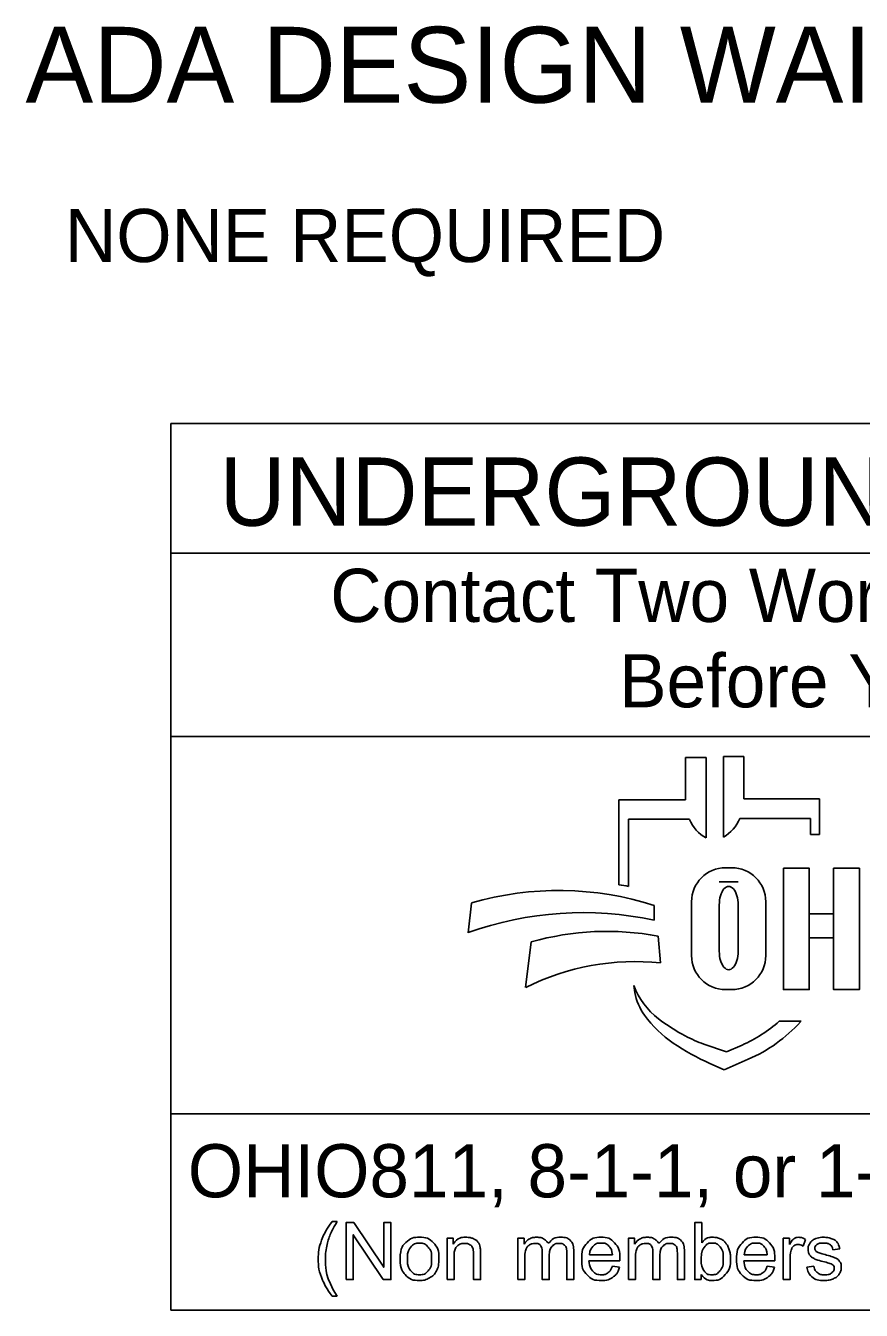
# Model space of a CAD drawing. Extents: x 0 to 40.2, y 0 to 22.
# Drawn here: x 1.995 to 4.196, y 2.143 to 5.529 of the extents above; entities that cross this region are included whole.
import ezdxf

# ---------------------------------------------------------------- set-up
doc = ezdxf.new("R2010")
doc.units = 0
doc.layers.add('GM_X_Adjacent_County', color=7, linetype='Continuous')
doc.layers.add('GM_X_Adjacent_County_Text', color=7, linetype='Continuous')

msp = doc.modelspace()

# ---------------------------------------------------------------- linework, layer by layer
at = {"layer": 'GM_X_Adjacent_County'}
for p, q in [((2.3775, 2.1428), (2.3775, 4.4803)), ((6.6275, 4.4803), (2.3775, 4.4803)), ((2.3775, 4.1387), (6.6275, 4.1387)), ((2.3775, 3.6553), (6.6275, 3.6553)), ((6.6275, 2.6607), (2.3775, 2.6607)), ((6.6275, 2.1428), (2.3775, 2.1428))]:
    msp.add_line(p, q, dxfattribs=at)
at = {"layer": 'GM_X_Adjacent_County_Text'}
for p, q in [((3.7335, 3.4883), (3.7335, 3.5998)), ((3.7335, 3.5998), (3.7872, 3.5998)), ((3.7872, 3.5998), (3.7872, 3.3877)), ((3.8329, 3.39), (3.8329, 3.6021)), ((3.8329, 3.6021), (3.8865, 3.6021)), ((3.8865, 3.6021), (3.8865, 3.4906)), ((3.5576, 3.2644), (3.5576, 3.4883)), ((3.5576, 3.4883), (3.7335, 3.4883)), ((3.8865, 3.4906), (4.0857, 3.4906)), ((4.0857, 3.4906), (4.0857, 3.3968)), ((3.5828, 3.4369), (3.5828, 3.26)), ((3.7439, 3.4369), (3.5828, 3.4369)), ((4.0625, 3.4392), (3.8761, 3.4392)), ((4.0625, 3.3968), (4.0625, 3.4392)), ((4.0857, 3.3968), (4.0625, 3.3968)), ((3.8385, 3.3091), (3.8551, 3.3091)), ((3.8718, 3.2721), (3.822, 3.2721)), ((3.7491, 3.0776), (3.7491, 3.2196)), ((3.9445, 3.2196), (3.9445, 3.0776)), ((3.1602, 3.1381), (3.1696, 3.2162)), ((3.6509, 3.2097), (3.6509, 3.1709)), ((3.822, 3.089), (3.822, 3.2114)), ((3.8718, 3.2114), (3.8718, 3.089)), ((3.6608, 3.1291), (3.6671, 3.0582)), ((3.312, 2.9936), (3.3267, 3.1137)), ((3.5997, 2.9807), (3.5967, 2.9986)), ((3.8551, 2.9882), (3.8385, 2.9882)), ((3.98, 2.9048), (4.0375, 2.9048)), ((3.7816, 2.8444), (3.841, 2.8239)), ((3.841, 2.8239), (3.8821, 2.8417)), ((3.835, 2.7769), (3.7976, 2.7934)), ((3.8983, 2.8044), (3.835, 2.7769))]:
    msp.add_line(p, q, dxfattribs=at)
for points in [[(3.991, 3.3081), (4.0589, 3.3081), (4.0589, 2.9881), (3.991, 2.9881)], [(4.1231, 3.3081), (4.1911, 3.3081), (4.1911, 2.9881), (4.1231, 2.9881)], [(4.0589, 3.1882), (4.1231, 3.1882), (4.1231, 3.1242), (4.0589, 3.1242)]]:
    msp.add_lwpolyline(points, close=True, dxfattribs=at)
for points in [[(2.8021, 2.3766), (2.8153, 2.3766)], [(2.8389, 2.2239), (2.8389, 2.3741), (2.8592, 2.3741), (2.9382, 2.2561), (2.9382, 2.3741), (2.9572, 2.3741), (2.9572, 2.2239), (2.9369, 2.2239), (2.8579, 2.3419), (2.8579, 2.2239), (2.8389, 2.2239)], [(3.7743, 2.2239), (3.7573, 2.2239), (3.7573, 2.3741), (3.7757, 2.3741), (3.7757, 2.3206)], [(3.1048, 2.2239), (3.1048, 2.3328), (3.1214, 2.3328), (3.1214, 2.3173)], [(3.2912, 2.2239), (3.2912, 2.3328), (3.3077, 2.3328), (3.3077, 2.3174)], [(3.5826, 2.2239), (3.5826, 2.3328), (3.5991, 2.3328), (3.5991, 2.3174)], [(3.9904, 2.2239), (3.9904, 2.3328), (4.007, 2.3328), (4.007, 2.3163)], [(4.0495, 2.3293), (4.043, 2.3122)], [(4.1394, 2.3046), (4.1213, 2.3022)], [(3.1233, 2.2833), (3.1233, 2.2239), (3.1048, 2.2239)], [(3.1932, 2.2908), (3.1932, 2.2239), (3.1748, 2.2239), (3.1748, 2.2901)], [(3.3097, 2.2803), (3.3097, 2.2239), (3.2912, 2.2239)], [(3.3743, 2.2871), (3.3743, 2.2239), (3.3559, 2.2239), (3.3559, 2.2946)], [(3.4388, 2.2986), (3.4388, 2.2239), (3.4203, 2.2239), (3.4203, 2.2924)], [(3.56, 2.2736), (3.4788, 2.2736)], [(3.4799, 2.2887), (3.5406, 2.2887)], [(3.601, 2.2803), (3.601, 2.2239), (3.5826, 2.2239)], [(3.6657, 2.2871), (3.6657, 2.2239), (3.6473, 2.2239), (3.6473, 2.2946)], [(3.7301, 2.2986), (3.7301, 2.2239), (3.7117, 2.2239), (3.7117, 2.2924)], [(3.968, 2.2736), (3.8868, 2.2736)], [(3.8879, 2.2887), (3.9486, 2.2887)], [(4.0088, 2.2809), (4.0088, 2.2239), (3.9904, 2.2239)], [(3.5404, 2.2591), (3.5595, 2.2567)], [(3.7743, 2.2375), (3.7743, 2.2239)], [(3.9484, 2.2591), (3.9675, 2.2567)], [(4.053, 2.2564), (4.0712, 2.2593)], [(2.8153, 2.1798), (2.8021, 2.1798)]]:
    msp.add_lwpolyline(points, dxfattribs=at)
for centre, radius, start, end in [((3.8353, 3.4736), 0.0985, 201.9296, 240.7469), ((3.7847, 3.476), 0.0985, 299.2531, 338.0704), ((3.8385, 3.2196), 0.0895, 90, 180), ((3.8551, 3.2196), 0.0895, 0, 90), ((3.4295, 2.4554), 0.8191, 79.2074, 81.0007), ((3.3997, 2.4302), 0.8191, 72.1402, 106.3144), ((3.4628, 2.2991), 0.8919, 77.8238, 109.8274), ((3.5267, 2.4094), 0.7322, 79.44, 105.8467), ((3.5987, 2.4262), 0.6357, 83.8248, 116.8021), ((3.8385, 3.0776), 0.0895, 180, 270), ((3.8551, 3.0776), 0.0895, 270, 0), ((3.7841, 3.0707), 0.2008, 201.0457, 232.5314), ((3.741, 3.0048), 0.1433, 189.6817, 216.0884), ((3.8747, 3.1022), 0.3088, 216.0884, 235.7167), ((3.9766, 3.3219), 0.5173, 232.5314, 241.794), ((3.7387, 3.1722), 0.3602, 293.4582, 312.0712), ((3.7387, 3.1722), 0.401, 293.4582, 317.8286), ((4.0412, 3.3465), 0.6044, 235.7167, 246.2325), ((3.8914, 3.1631), 0.3371, 241.794, 250.9821)]:
    msp.add_arc(centre, radius, start, end, dxfattribs=at)
for centre, start_param, end_param in [((3.8469, 3.2114), 4.712389, 7.853982), ((3.8469, 3.089), 1.570796, 4.712389)]:
    msp.add_ellipse(centre, major_axis=(0, 0.0484), ratio=0.514403, start_param=start_param, end_param=end_param, dxfattribs=at)
for points in [[(2.8021, 2.1798), (2.7869, 2.199), (2.7763, 2.2248), (2.7657, 2.2506), (2.7657, 2.2783), (2.7657, 2.3026), (2.7736, 2.325), (2.7829, 2.3509), (2.8021, 2.3766)], [(2.8153, 2.3766), (2.8029, 2.3553), (2.7989, 2.3462), (2.7927, 2.332), (2.7891, 2.3167), (2.7847, 2.2975), (2.7847, 2.2782), (2.7847, 2.2289), (2.8153, 2.1798)], [(2.9814, 2.2783), (2.9814, 2.3085), (2.9981, 2.3231), (3.0122, 2.3352), (3.0323, 2.3352), (3.0547, 2.3352), (3.069, 2.3205), (3.0832, 2.3058), (3.0832, 2.2799), (3.0832, 2.2589), (3.0769, 2.2469), (3.0706, 2.2348), (3.0586, 2.2282), (3.0466, 2.2215), (3.0323, 2.2215), (3.0095, 2.2215), (2.9954, 2.2362), (2.9814, 2.2508), (2.9814, 2.2783)], [(3.0003, 2.2783), (3.0003, 2.2574), (3.0094, 2.247), (3.0185, 2.2366), (3.0323, 2.2366), (3.046, 2.2366), (3.0551, 2.2471), (3.0642, 2.2575), (3.0642, 2.279), (3.0642, 2.2991), (3.0551, 2.3095), (3.0459, 2.3199), (3.0323, 2.3199), (3.0185, 2.3199), (3.0094, 2.3096), (3.0003, 2.2992), (3.0003, 2.2783)], [(3.1214, 2.3173), (3.1334, 2.3352), (3.156, 2.3352), (3.1659, 2.3352), (3.1741, 2.3316), (3.1823, 2.3281), (3.1864, 2.3224), (3.1905, 2.3166), (3.1922, 2.3087), (3.1932, 2.3036), (3.1932, 2.2908)], [(3.1748, 2.2901), (3.1748, 2.3013), (3.1726, 2.3069), (3.1705, 2.3125), (3.165, 2.3158), (3.1595, 2.3191), (3.1521, 2.3191), (3.1404, 2.3191), (3.1318, 2.3117), (3.1233, 2.3042), (3.1233, 2.2833)], [(3.3077, 2.3174), (3.3128, 2.3254), (3.3214, 2.3303), (3.3299, 2.3352), (3.3407, 2.3352), (3.3528, 2.3352), (3.3606, 2.3301), (3.3683, 2.3251), (3.3715, 2.3161), (3.3844, 2.3352), (3.4051, 2.3352), (3.4213, 2.3352), (3.43, 2.3262), (3.4388, 2.3172), (3.4388, 2.2986)], [(3.3559, 2.2946), (3.3559, 2.3069), (3.3514, 2.313), (3.3469, 2.3191), (3.3366, 2.3191), (3.3288, 2.3191), (3.3222, 2.315), (3.3156, 2.311), (3.3126, 2.3031), (3.3097, 2.2952), (3.3097, 2.2803)], [(3.4203, 2.2924), (3.4203, 2.3035), (3.4185, 2.3083), (3.4168, 2.3132), (3.412, 2.3162), (3.4073, 2.3191), (3.401, 2.3191), (3.3895, 2.3191), (3.3819, 2.3115), (3.3743, 2.3039), (3.3743, 2.2871)], [(3.5595, 2.2567), (3.555, 2.24), (3.5428, 2.2307), (3.5306, 2.2215), (3.5117, 2.2215), (3.4878, 2.2215), (3.4738, 2.2362), (3.4598, 2.2509), (3.4598, 2.2774), (3.4598, 2.3049), (3.474, 2.32), (3.4881, 2.3352), (3.5106, 2.3352), (3.5324, 2.3352), (3.5463, 2.3203), (3.5601, 2.3055), (3.5601, 2.2785), (3.5601, 2.2769), (3.56, 2.2736)], [(3.5406, 2.2887), (3.5394, 2.3025), (3.5337, 2.3094), (3.5249, 2.3201), (3.5108, 2.3201), (3.4981, 2.3201), (3.4894, 2.3115), (3.4808, 2.303), (3.4799, 2.2887)], [(3.5991, 2.3174), (3.6042, 2.3254), (3.6127, 2.3303), (3.6212, 2.3352), (3.6321, 2.3352), (3.6442, 2.3352), (3.6519, 2.3301), (3.6597, 2.3251), (3.6628, 2.3161), (3.6758, 2.3352), (3.6965, 2.3352), (3.7127, 2.3352), (3.7214, 2.3262), (3.7301, 2.3172), (3.7301, 2.2986)], [(3.6473, 2.2946), (3.6473, 2.3069), (3.6428, 2.313), (3.6383, 2.3191), (3.628, 2.3191), (3.6202, 2.3191), (3.6136, 2.315), (3.607, 2.311), (3.604, 2.3031), (3.601, 2.2952), (3.601, 2.2803)], [(3.7117, 2.2924), (3.7117, 2.3035), (3.7099, 2.3083), (3.7081, 2.3132), (3.7034, 2.3162), (3.6987, 2.3191), (3.6923, 2.3191), (3.6809, 2.3191), (3.6733, 2.3115), (3.6657, 2.3039), (3.6657, 2.2871)], [(3.7741, 2.2792), (3.7741, 2.2596), (3.7794, 2.2509), (3.7881, 2.2366), (3.8029, 2.2366), (3.815, 2.2366), (3.8238, 2.2471), (3.8326, 2.2576), (3.8326, 2.2784), (3.8326, 2.2998), (3.8241, 2.3099), (3.8157, 2.3201), (3.8038, 2.3201), (3.7917, 2.3201), (3.7829, 2.3096), (3.7741, 2.299), (3.7741, 2.2792)], [(3.7757, 2.3206), (3.7874, 2.3352), (3.8055, 2.3352), (3.8155, 2.3352), (3.8245, 2.3311), (3.8335, 2.3271), (3.8392, 2.3198), (3.845, 2.3124), (3.8483, 2.3021), (3.8516, 2.2918), (3.8516, 2.28), (3.8516, 2.252), (3.8378, 2.2368), (3.8239, 2.2215), (3.8046, 2.2215), (3.7853, 2.2215), (3.7743, 2.2375)], [(3.9675, 2.2567), (3.963, 2.24), (3.9508, 2.2307), (3.9386, 2.2215), (3.9196, 2.2215), (3.8958, 2.2215), (3.8818, 2.2362), (3.8678, 2.2509), (3.8678, 2.2774), (3.8678, 2.3049), (3.882, 2.32), (3.8961, 2.3352), (3.9186, 2.3352), (3.9404, 2.3352), (3.9543, 2.3203), (3.9681, 2.3055), (3.9681, 2.2785), (3.9681, 2.2769), (3.968, 2.2736)], [(3.9486, 2.2887), (3.9474, 2.3025), (3.9417, 2.3094), (3.9328, 2.3201), (3.9188, 2.3201), (3.9061, 2.3201), (3.8974, 2.3115), (3.8888, 2.303), (3.8879, 2.2887)], [(4.007, 2.3163), (4.0133, 2.3278), (4.0187, 2.3315), (4.0241, 2.3352), (4.0305, 2.3352), (4.0398, 2.3352), (4.0495, 2.3293)], [(4.043, 2.3122), (4.0363, 2.3162), (4.0295, 2.3162), (4.0235, 2.3162), (4.0187, 2.3125), (4.0139, 2.3089), (4.0119, 2.3024), (4.0088, 2.2926), (4.0088, 2.2809)], [(4.1213, 2.3022), (4.1201, 2.3106), (4.1142, 2.3153), (4.1083, 2.3201), (4.0975, 2.3201), (4.0848, 2.3201), (4.0794, 2.3159), (4.0739, 2.3116), (4.0739, 2.306), (4.0739, 2.3024), (4.0762, 2.2995), (4.0785, 2.2966), (4.0833, 2.2946), (4.086, 2.2936), (4.0996, 2.2899), (4.1192, 2.2847), (4.1269, 2.2813), (4.1347, 2.278), (4.1391, 2.2717), (4.1435, 2.2653), (4.1435, 2.2559), (4.1435, 2.2467), (4.1381, 2.2386), (4.1327, 2.2304), (4.1226, 2.226), (4.1124, 2.2215), (4.0996, 2.2215), (4.0784, 2.2215), (4.0672, 2.2303), (4.0561, 2.2391), (4.053, 2.2564)], [(4.0712, 2.2593), (4.0727, 2.2483), (4.0798, 2.2425), (4.0868, 2.2366), (4.0995, 2.2366), (4.1122, 2.2366), (4.1184, 2.2418), (4.1245, 2.247), (4.1245, 2.254), (4.1245, 2.2602), (4.1191, 2.2638), (4.1153, 2.2663), (4.1002, 2.2701), (4.0799, 2.2752), (4.072, 2.2789), (4.0642, 2.2827), (4.0601, 2.2893), (4.0561, 2.2959), (4.0561, 2.3038), (4.0561, 2.3111), (4.0594, 2.3173), (4.0628, 2.3235), (4.0685, 2.3276), (4.0728, 2.3308), (4.0803, 2.333), (4.0877, 2.3352), (4.0962, 2.3352), (4.109, 2.3352), (4.1187, 2.3315), (4.1284, 2.3278), (4.133, 2.3215), (4.1377, 2.3152), (4.1394, 2.3046)], [(3.4788, 2.2736), (3.4799, 2.2557), (3.489, 2.2462), (3.4981, 2.2366), (3.5117, 2.2366), (3.5219, 2.2366), (3.5291, 2.242), (3.5362, 2.2473), (3.5404, 2.2591)], [(3.8868, 2.2736), (3.8879, 2.2557), (3.897, 2.2462), (3.9061, 2.2366), (3.9197, 2.2366), (3.9299, 2.2366), (3.937, 2.242), (3.9442, 2.2473), (3.9484, 2.2591)]]:
    msp.add_open_spline(points, degree=3, dxfattribs=at)

# ---------------------------------------------------------------- texts
for s, height, p in [('ADA DESIGN WAIVERS', 0.2, (1.9944, 5.3256)), ('  NONE REQUIRED                          ', 0.14, (1.9944, 4.9056)), ('UNDERGROUND UTILITIES', 0.18, (2.5057, 4.2106)), ('Contact Two Working Days', 0.14, (2.7972, 3.9571)), ('Before You Dig', 0.14, (3.5583, 3.7321)), ('OHIO811, 8-1-1, or 1-800-362-2764', 0.14, (2.422, 2.4406))]:
    msp.add_text(s, height=height, dxfattribs=at).set_placement(p)

doc.saveas('drawing.dxf')
